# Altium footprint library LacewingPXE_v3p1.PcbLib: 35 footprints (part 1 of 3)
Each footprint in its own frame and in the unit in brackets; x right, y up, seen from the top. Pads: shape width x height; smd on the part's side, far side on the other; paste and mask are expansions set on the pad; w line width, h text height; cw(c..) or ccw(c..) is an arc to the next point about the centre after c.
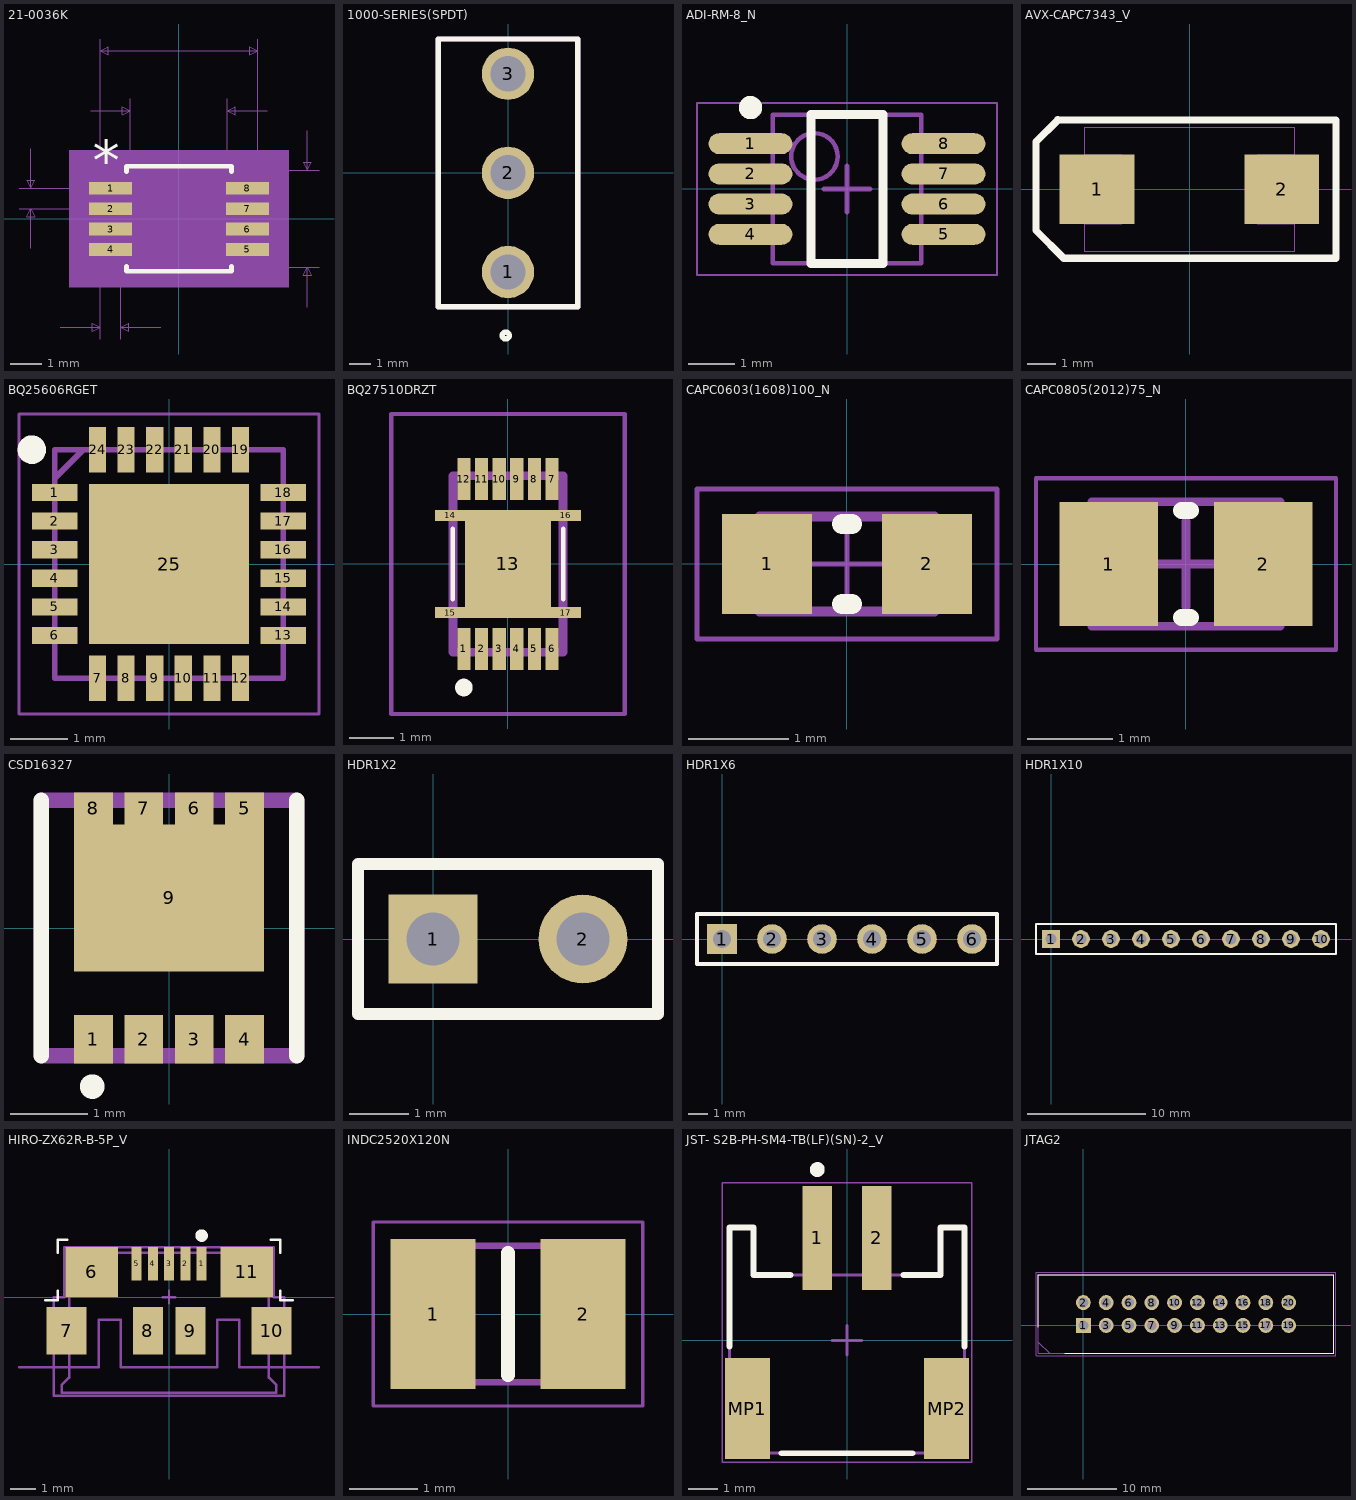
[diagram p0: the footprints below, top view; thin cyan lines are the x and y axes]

## 21-0036K [mil]
pads (8):
  rect 54x16 smd paste+0 mask+0: 1(-86,38.39) 2(-86,12.8) 3(-86,-12.8) 4(-86,-38.39) 5(86,-38.39) 6(86,-12.8) 7(86,12.8) 8(86,38.39)
Top Overlay:
  lines w6: -66,-59.49 -66,-66 66,-66 66,-59.49 ; -66,59.49 -66,66 66,66 66,59.49
  text "*" at -108.5,49.39 h50
Mechanical 5:
  region: 138,-86 -138,-86 -138,86 138,86
Mechanical 7:
  lines w1: -201,12.8 -86,12.8 ; -201,38.39 -86,38.39 ; -186,-37.2 -186,12.8 ; -186,88.39 -186,38.39 ; -149,-136 -99,-136 ; -111,136 -61,136 ; -99,-151 -99,0 -99,226 ; -73,-151 -73,0 ; -61,0 -61,151 ; -23,-136 -73,-136 ; 0,-61 176,-61 ; 0,61 176,61 ; 61,0 61,151 ; 99,0 99,226 ; 111,136 61,136 ; 161,-111 161,-61 ; 161,111 161,61 ; -186,12.8 -191,2.8 -181,2.8 -186,12.8 ; -186,38.39 -191,48.39 -181,48.39 -186,38.39 ; -99,-136 -109,-131 -109,-141 -99,-136 ; -99,211 99,211 ; -99,211 -89,216 -89,206 -99,211 ; -73,-136 -63,-131 -63,-141 -73,-136 ; -61,136 -71,141 -71,131 -61,136 ; 61,136 71,141 71,131 61,136 ; 99,211 89,216 89,206 99,211 ; 161,-61 156,-71 166,-71 161,-61 ; 161,61 156,71 166,71 161,61
  text "Default Padstyle: RX54Y16D0T" at -350,-261 h50
  text "Pin One Padstyle: RX54Y16D0T" at -350,-321 h50
  text "Alt 1 Padstyle: OX60Y90D30P" at -337.5,-501 h50
  text "Alt 2 Padstyle: OX90Y60D30P" at -337.5,-561 h50
  text "0.122in/3.099mm" at -93.75,156 h25
  text "0.198in/5.029mm" at -93.75,231 h25
  text "0.122in/3.099mm" at 181,-12.5 h25
  text "0.026in/0.65mm" at -381,13.09 h25
  text "0.026in/0.66mm" at -173.5,-181 h25
Mechanical 13:
  lines w0: -12,61 ccw(c0,61) 12,61
  lines w1: -99,-45.39 -99,-31.39 -61,-31.39 -61,-45.39 -99,-45.39 ; -99,-19.8 -99,-5.8 -61,-5.8 -61,-19.8 -99,-19.8 ; -99,5.8 -99,19.8 -61,19.8 -61,5.8 -99,5.8 ; -99,31.39 -99,45.39 -61,45.39 -61,31.39 -99,31.39 ; -61,-61 61,-61 61,61 -61,61 -61,-61 ; 61,-45.39 61,-31.39 99,-31.39 99,-45.39 61,-45.39 ; 61,-19.8 61,-5.8 99,-5.8 99,-19.8 61,-19.8 ; 61,5.8 61,19.8 99,19.8 99,5.8 61,5.8 ; 61,31.39 61,45.39 99,45.39 99,31.39 61,31.39
  text "*" at -58.5,8 h50
Mechanical 15:
  region: -71,-56.39 -123,-56.39 -123,56.39 -71,56.39 -71,71 71,71 71,56.39 123,56.39 123,-56.39 71,-56.39 71,-71 -71,-71
  lines w6: -123,-56.39 -123,56.39 -71,56.39 -71,71 71,71 71,56.39 123,56.39 123,-56.39 71,-56.39 71,-71 -71,-71 -71,-56.39 -123,-56.39
3D body: height 10, standoff 0, extent 0,0 10,10

## 1000-SERIES(SPDT) [mm]
pads (3):
  round 2.48 hole 1.68: 1(0,-4.7) 2(0,0) 3(0,4.7)
Top Overlay:
  circle w0.254: c-0.109,-7.714 r0.164
  lines w0.254: -3.3,-6.35 -3.3,6.35 3.3,6.35 3.3,-6.35 -3.3,-6.35
Mechanical 13:
  lines w0.254: -3.3,-6.35 3.3,-6.35 3.3,6.35 -3.3,6.35 -3.3,-6.35

## ADI-RM-8_N [mm] "SOP, 8-Leads, Body 3x3mm, Pitch 0.65mm, IPC Medium Density"
height 1.1
pads (8):
  oval 1.8x0.45 smd: 1(-2.075,0.975) 2(-2.075,0.325) 3(-2.075,-0.325) 4(-2.075,-0.975) 5(2.075,-0.975) 6(2.075,-0.325) 7(2.075,0.325) 8(2.075,0.975)
Top Overlay:
  circle w0.25: c-2.075,1.75 r0.125
  lines w0.2: -0.775,-1.6 -0.775,1.6 0.775,1.6 0.775,-1.6 -0.775,-1.6
Mechanical 13:
  circle w0.1: c-0.7,0.7 r0.5
  lines w0.1: -1.6,-1.6 -1.6,1.6 1.6,1.6 1.6,-1.6 -1.6,-1.6
Mechanical 15:
  lines w0.05: -3.225,-1.85 -3.225,1.85 3.225,1.85 3.225,-1.85 -3.225,-1.85
  lines w0.1: -0.5,0 0.5,0 ; 0,-0.5 0,0.5
3D body: height 1.1, standoff 0, extent -1.6,-1.6 1.6,1.6

## AVX-CAPC7343_V [mm] "SMT Capacitor, 2 Leads, Body 7.3x4.3mm"
pads (2):
  rect 2.6x2.4 smd: 1(-3.202,0.007) 2(3.198,0.007)
Top Overlay:
  lines w0.254: -4.575,2.4 -5.325,1.65 -5.325,-1.425 -4.362,-2.388 ; -4.572,2.413 5.08,2.406 ; -4.369,-2.388 5.08,-2.388 5.08,2.388
Mechanical 7:
  lines w0.025: -3.651,-1.192 -2.351,-1.192 -2.351,1.208 -3.651,1.208 ; 3.649,-1.192 2.349,-1.192 2.349,1.208 3.649,1.208 ; -3.651,-2.142 3.649,-2.142 3.649,2.158 -3.651,2.158 -3.651,-2.142
  text ".Designator" at -3.575,1.375 h0.6
  text ".Comment" at -3.575,-2.025 h0.6
3D body: height 0.3, standoff 0, extent 3.308,-0.855 3.512,0.915
3D body: height 0.3, standoff 0, extent -3.487,-0.869 -3.392,0.82
3D body: height 2.9, standoff 0, extent -3.464,-2.032 3.481,2.039
3D body: height 4.05, standoff 3.9, extent -2.468,-2.017 -1.993,2.005

## BQ25606RGET [mm] "QFN50P400X400X100-25N"
pads (25):
  rect 0.8x0.3 smd: 1(-2,1.25) 2(-2,0.75) 3(-2,0.25) 4(-2,-0.25) 5(-2,-0.75) 6(-2,-1.25) 13(2,-1.25) 14(2,-0.75) 15(2,-0.25) 16(2,0.25) 17(2,0.75) 18(2,1.25)
  rect 0.3x0.8 smd: 7(-1.25,-2) 8(-0.75,-2) 9(-0.25,-2) 10(0.25,-2) 11(0.75,-2) 12(1.25,-2) 19(1.25,2) 20(0.75,2) 21(0.25,2) 22(-0.25,2) 23(-0.75,2) 24(-1.25,2)
  rect 2.8x2.8 smd: 25(0,0)
Top Overlay:
  circle w0.25: c-2.4,2 r0.125
Mechanical 13:
  lines w0.1: -2,1.5 -1.5,2 ; -2,-2 -2,2 2,2 2,-2 -2,-2
Mechanical 15:
  lines w0.05: -2.625,-2.625 -2.625,2.625 2.625,2.625 2.625,-2.625 -2.625,-2.625
3D body "BQ25606RGET.stp": height 1, standoff 0, extent -2.05,-2.05 2.05,2.05

## BQ27510DRZT [mm]
pads (17):
  rect 0.3x0.95 smd: 1(-1,-1.925) 2(-0.6,-1.925) 3(-0.2,-1.925) 4(0.2,-1.925) 5(0.6,-1.925) 6(1,-1.925) 7(1,1.925) 8(0.6,1.925) 9(0.2,1.925) 10(-0.2,1.925) 11(-0.6,1.925) 12(-1,1.925)
  rect 1.95x2.45 smd: 13(0,0)
  rect 0.675x0.25 smd: 14(-1.313,1.1) 15(-1.313,-1.1) 16(1.313,1.1) 17(1.313,-1.1)
Top Overlay:
  lines w0.1: -1.25,-0.8 -1.25,0.8 ; 1.25,-0.8 1.25,0.8
  lines w0.2: -1.1,-2.8 cw(c-1,-2.8) -0.9,-2.8 cw(c-1,-2.8) -1.1,-2.8
Mechanical 13:
  lines w0.2: -1.25,-2 -1.25,2 1.25,2 1.25,-2 -1.25,-2
Mechanical 15:
  lines w0.1: -2.65,-3.4 -2.65,3.4 2.65,3.4 2.65,-3.4 -2.65,-3.4

## CAPC0603(1608)100_N [mm] "Chip Capacitor, Body 1.6x0.8mm, Height 1.0mm, IPC Medium Density"
height 1
pads (2):
  rect 0.9x1 smd: 1(-0.8,0) 2(0.8,0)
Top Overlay:
  lines w0.2: -0.05,-0.4 0.05,-0.4 ; -0.05,0.4 0.05,0.4
Mechanical 13:
  lines w0.1: -0.875,-0.475 -0.875,0.475 0.875,0.475 0.875,-0.475 -0.875,-0.475
Mechanical 15:
  lines w0.05: -0.475,0 0.475,0 ; 0,-0.475 0,0.475 ; -1.5,-0.75 -1.5,0.75 1.5,0.75 1.5,-0.75 -1.5,-0.75
3D body: height 1, standoff 0, extent -0.525,-0.475 0.525,0.475
3D body: height 1, standoff 0, extent -0.875,-0.475 -0.525,0.475
3D body: height 1, standoff 0, extent 0.525,-0.475 0.875,0.475

## CAPC0805(2012)75_N [mm] "Chip Capacitor, Body 2.0x1.2mm, Height 0.75mm, IPC Medium Density"
height 0.75
pads (2):
  rect 1.15x1.45 smd: 1(-0.9,0) 2(0.9,0)
Top Overlay:
  lines w0.2: -0.05,-0.625 0.05,-0.625 ; -0.05,0.625 0.05,0.625
Mechanical 13:
  lines w0.1: -1.1,-0.725 -1.1,0.725 1.1,0.725 1.1,-0.725 -1.1,-0.725
Mechanical 15:
  lines w0.05: -1.75,-1 -1.75,1 1.75,1 1.75,-1 -1.75,-1
  lines w0.1: -0.5,0 0.5,0 ; 0,-0.5 0,0.5
3D body: height 0.75, standoff 0, extent -0.6,-0.725 0.6,0.725
3D body: height 0.75, standoff 0, extent -1.1,-0.725 -0.6,0.725
3D body: height 0.75, standoff 0, extent 0.6,-0.725 1.1,0.725

## CSD16327 [mm] "CSD17575Q3"
pads (9):
  rect 0.5x0.63 smd: 1(-0.975,-1.435) 2(-0.325,-1.435) 3(0.325,-1.435) 4(0.975,-1.435)
  rect 0.5x0.41 smd: 5(0.975,1.545) 6(0.325,1.545) 7(-0.325,1.545) 8(-0.975,1.545)
  rect 2.45x1.9 smd: 9(0,0.39)
Top Overlay:
  circle w0.254: c-0.99,-2.045 r0.031
  lines w0.2: -1.65,-1.65 -1.65,1.65 ; 1.65,-1.65 1.65,1.65
Mechanical 13:
  lines w0.2: -1.65,-1.65 1.65,-1.65 1.65,1.65 -1.65,1.65 -1.65,-1.65

## HDR1X2 [mm] "Connector; Header; 2 Position"
pads (2):
  rect 1.5x1.5 hole 0.9: 1(0,0)
  round 1.5 hole 0.9: 2(2.54,0)
Top Overlay:
  lines w0.2: -1.27,-1.27 3.81,-1.27 3.81,1.27 -1.27,1.27 -1.27,-1.27

## HDR1X6 [mm] "Connector; Header; 6 Position"
pads (6):
  rect 1.5x1.5 hole 0.9: 1(0,0)
  round 1.5 hole 0.9: 2(2.54,0) 3(5.08,0) 4(7.62,0) 5(10.16,0) 6(12.7,0)
Top Overlay:
  lines w0.2: -1.27,-1.27 -1.27,1.27 13.97,1.27 13.97,-1.27 -1.27,-1.27

## HDR1X10 [mm] "Connector; Header; 10 Position"
pads (10):
  rect 1.5x1.5 hole 0.9: 1(0,0)
  round 1.5 hole 0.9: 2(2.54,0) 3(5.08,0) 4(7.62,0) 5(10.16,0) 6(12.7,0) 7(15.24,0) 8(17.78,0) 9(20.32,0) 10(22.86,0)
Top Overlay:
  lines w0.2: -1.27,-1.27 24.13,-1.27 24.13,1.27 0.635,1.27 -1.27,1.27 -1.27,-1.27

## HIRO-ZX62R-B-5P_V [mm] "USB Micro-B R/A Connector"
height 2.65
pads (11):
  rect 0.4x1.35 smd: 1(1.3,1.338) 2(0.65,1.338) 3(0,1.338) 4(-0.65,1.338) 5(-1.3,1.338)
  rect 2.1x2 smd: 6(-3.1,1.012) 11(3.1,1.012)
  rect 1.6x1.9 smd: 7(-4.1,-1.338) 10(4.1,-1.338)
  rect 1.2x1.9 smd: 8(-0.85,-1.338) 9(0.85,-1.338)
Top Overlay:
  circle w0.25: c1.304,2.46 r0.125
  lines w0.1: -4.953,-0.127 -4.445,-0.127 -4.445,0.254 ; -4.445,1.778 -4.445,2.286 -4.064,2.286 ; 4.064,2.286 4.445,2.286 4.445,1.778 ; 4.445,0.254 4.445,-0.127 4.953,-0.127
Mechanical 1:
  lines w0.1: -6,-2.8 -2.82,-2.8 -2.82,-0.9 -1.92,-0.9 -1.92,-2.8 0,-2.8 1.92,-2.8 1.92,-0.9 2.82,-0.9 2.82,-2.8 6,-2.8
  text "Board edge" at 5.588,-2.667 h0.2
Mechanical 13:
  lines w0.1: -4,1.78 4,1.78 ; -4,1.78 4,1.78 ; -4,1.78 -4,-0.72 -4.572,-0.72 -4.572,-1.778 -4,-1.778 -4,-3.22 -4.3,-3.52 -4.3,-3.82 4.3,-3.82 4.3,-3.52 4,-3.22 4,-1.778 4.572,-1.778 4.572,-0.72 4,-0.72 4,1.78
Mechanical 15:
  lines w0.1: -0.254,0 0.254,0 ; 0,-0.254 0,0.254 ; -4.6,-3.937 4.6,-3.937 4.6,-2.8 4.6,0 4.2,0 4.2,2 -4.2,2 -4.2,0 -4.6,0 -4.6,-2.8 -4.6,-3.937
3D body "ZX62R-B-5P.stp": height 2.71, standoff -0.23, extent -4.4,-3.953 4.4,1.778

## INDC2520X120N [mm]
pads (2):
  rect 1.25x2.2 smd: 1(-1.1,0) 2(1.1,0)
Top Overlay:
  lines w0.2: 0,-0.9 0,0.9
Mechanical 13:
  lines w0.1: -1.25,-1 -1.25,1 1.25,1 1.25,-1 -1.25,-1
Mechanical 15:
  lines w0.05: -1.975,-1.35 -1.975,1.35 1.975,1.35 1.975,-1.35 -1.975,-1.35
3D body "DFE252012F-1R0M=P2.stp": height 1.2, standoff 0, extent -1.25,-1 1.25,1

## JST- S2B-PH-SM4-TB(LF)(SN)-2_V [mm] "SMD, 2-Leads, Body 7.9x7.6mm, Pitch 2mm"
height 5.5
pads (4):
  rect 1x3.5 smd: 1(-1,3.45) 2(1,3.45)
  rect 1.5x3.4 smd: MP1(-3.35,-2.3) MP2(3.35,-2.3)
Top Overlay:
  circle w0.25: c-1,5.75 r0.125
  lines w0.2: -3.95,-0.2 -3.95,3.8 -3.15,3.8 -3.15,2.2 -1.9,2.2 ; -2.2,-3.8 2.2,-3.8 ; 1.9,2.2 3.15,2.2 3.15,3.8 3.95,3.8 3.95,-0.2
Mechanical 13:
  lines w0.1: -3.95,-3 -3.45,-3 -3.45,-3.8 3.45,-3.8 3.45,-3 3.95,-3 3.95,3.8 3.15,3.8 3.15,2.2 -3.15,2.2 -3.15,3.8 -3.95,3.8 -3.95,-3
Mechanical 15:
  lines w0.05: -4.2,-4.1 -4.2,5.3 4.2,5.3 4.2,-4.1 -4.2,-4.1
  lines w0.1: -0.5,0 0.5,0 ; 0,-0.5 0,0.5
3D body "S2B-PH-SM4-TB.STEP": height 5.6, standoff 0, extent -3.95,-3.8 3.95,4.8

## JTAG2 [mm] "Header, Vertical Shrouded, 100 mil pitch; 25 mil lead width, 20 pins, 2 rows, 10 pins per row, 1295 mil L X 346 mil W X 346 mil H body"
height 8.788
pads (20):
  rect 1.652x1.652 hole 1.101 paste-1.652: 1(0,0)
  round 1.652 hole 1.101 paste-1.652: 2(0,2.54) 3(2.54,0) 4(2.54,2.54) 5(5.08,0) 6(5.08,2.54) 7(7.62,0) 8(7.62,2.54) 9(10.16,0) 10(10.16,2.54) 11(12.7,0) 12(12.7,2.54) 13(15.24,0) 14(15.24,2.54) 15(17.78,0) 16(17.78,2.54) 17(20.32,0) 18(20.32,2.54) 19(22.86,0) 20(22.86,2.54)
Top Overlay:
  lines w0.127: -5.016,-0.195 -5.016,5.664 27.877,5.664 27.877,-3.124 -2.087,-3.124
Mechanical 11:
  lines w0.127: -5.016,-1.854 -5.016,5.664 27.877,5.664 27.877,-3.124 -3.746,-3.124 -5.016,-1.854
Mechanical 12:
  lines w0.025: -5.016,-3.124 27.877,-3.124 27.877,5.664 -5.016,5.664 -5.016,-3.124
Mechanical 15:
  circle w0.051: c0,0 r0.305
  lines w0.051: -0.406,0 0.406,0 ; 0,-0.406 0,0.406 ; -5.271,-3.378 28.13,-3.378 28.13,5.918 -5.271,5.918 -5.271,-3.378
3D body "TSS-110-01-G-D.step": height 8.89, standoff -3.3, extent -3.175,-3.556 26.035,5.918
